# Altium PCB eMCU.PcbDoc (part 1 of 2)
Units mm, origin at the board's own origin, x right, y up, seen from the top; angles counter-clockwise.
Board outline 90 x 58 mm, 2 copper layers (Top Layer, Bottom Layer); 104 components, 112 nets, 449 pads, 70 vias.
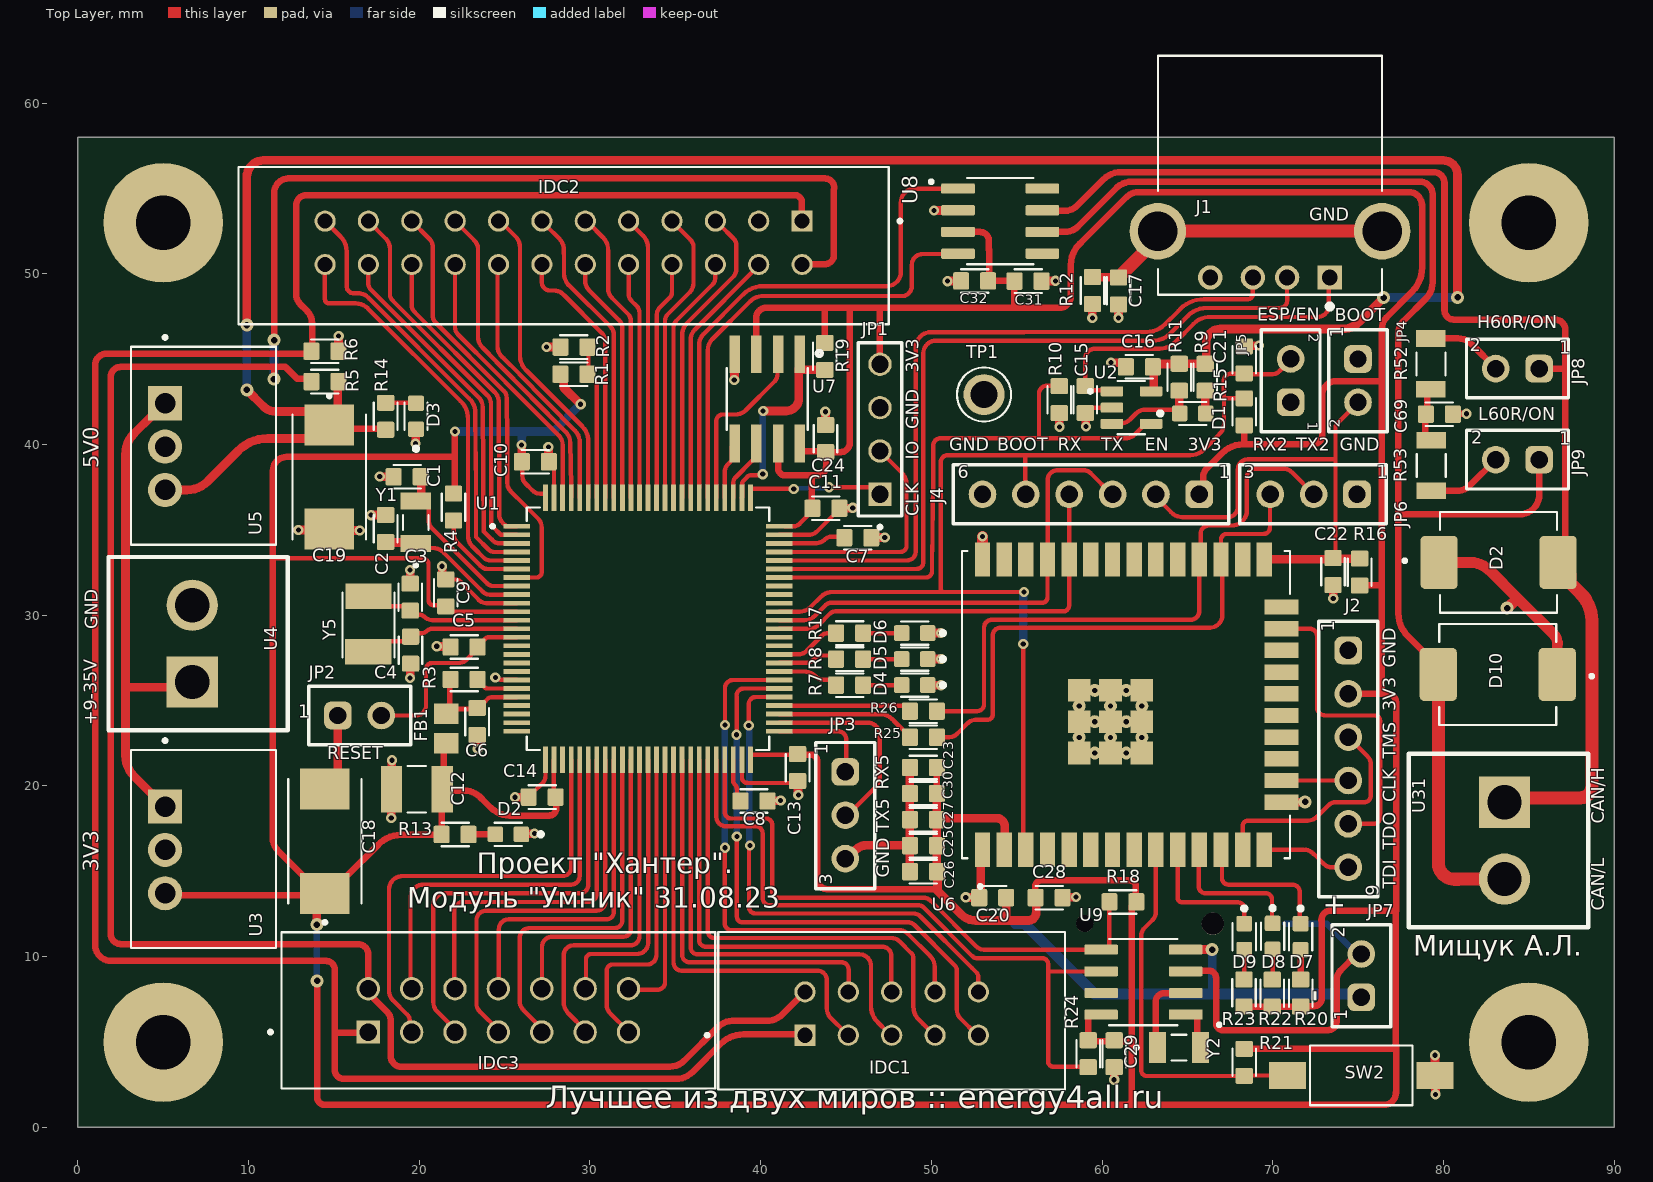
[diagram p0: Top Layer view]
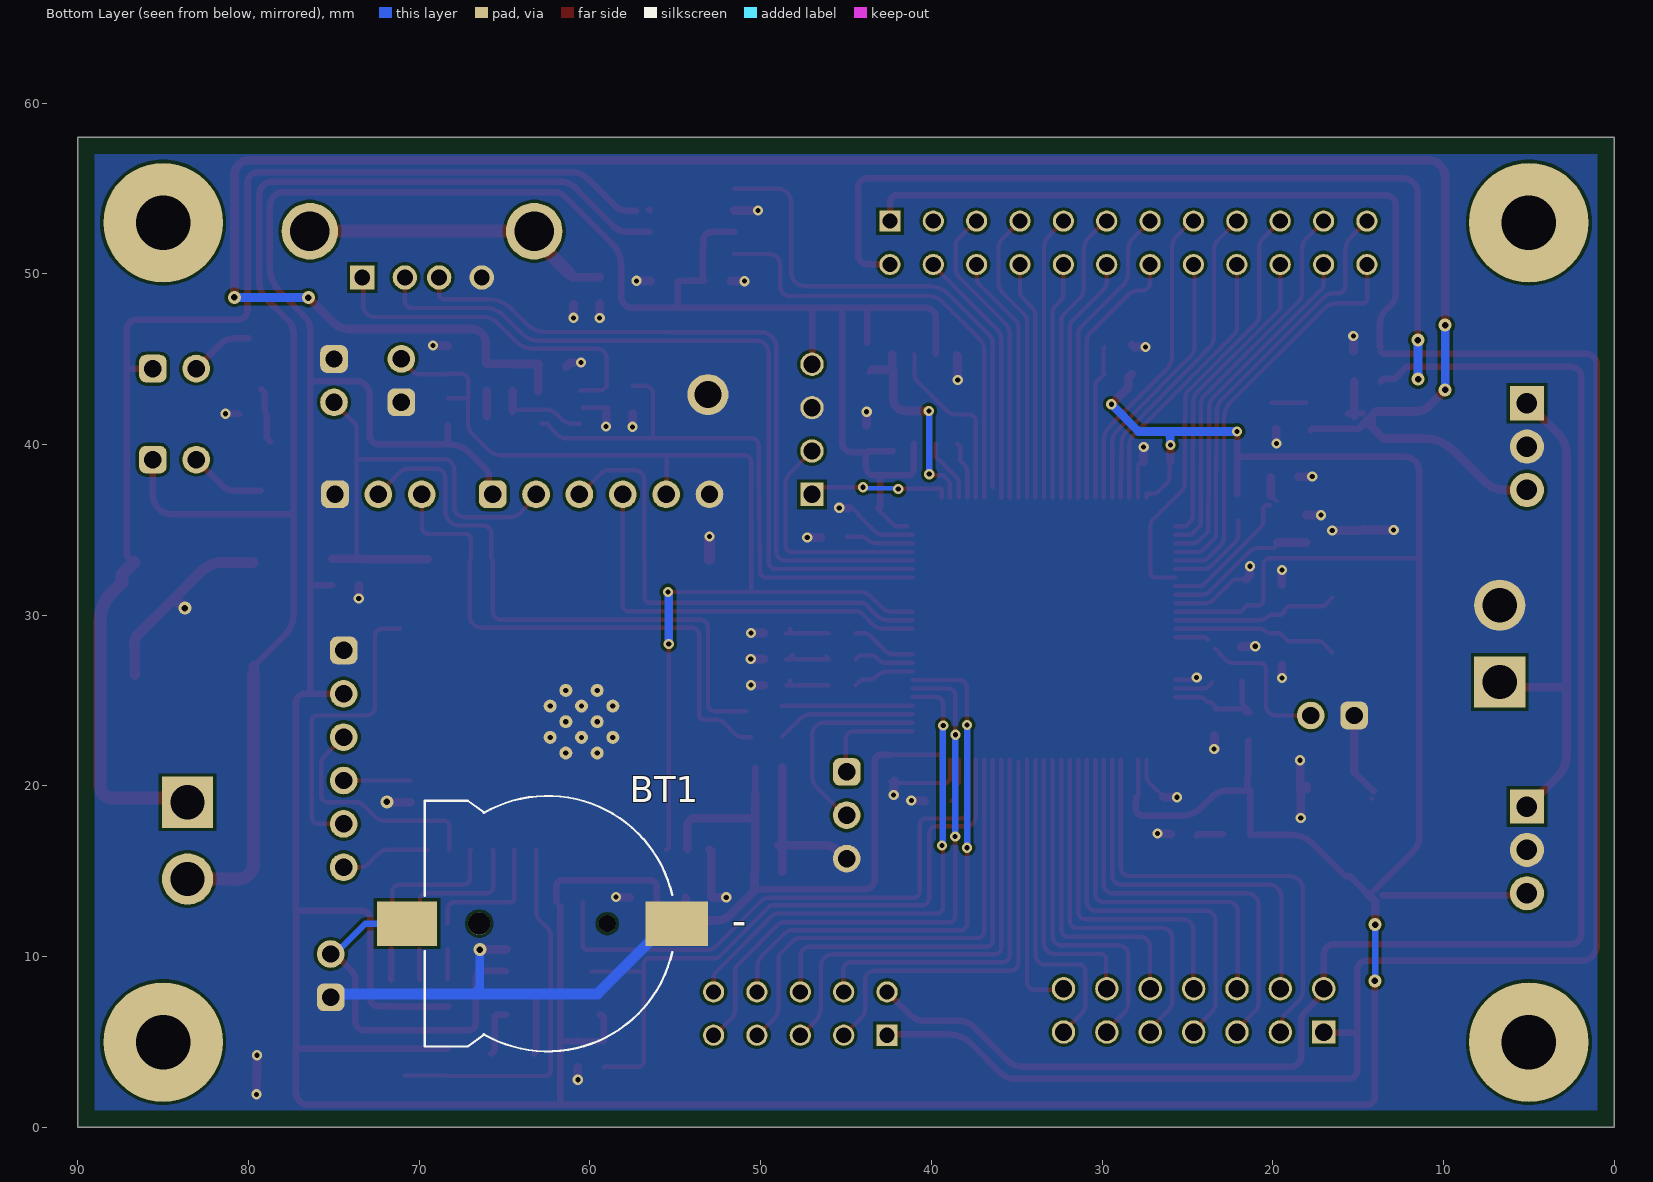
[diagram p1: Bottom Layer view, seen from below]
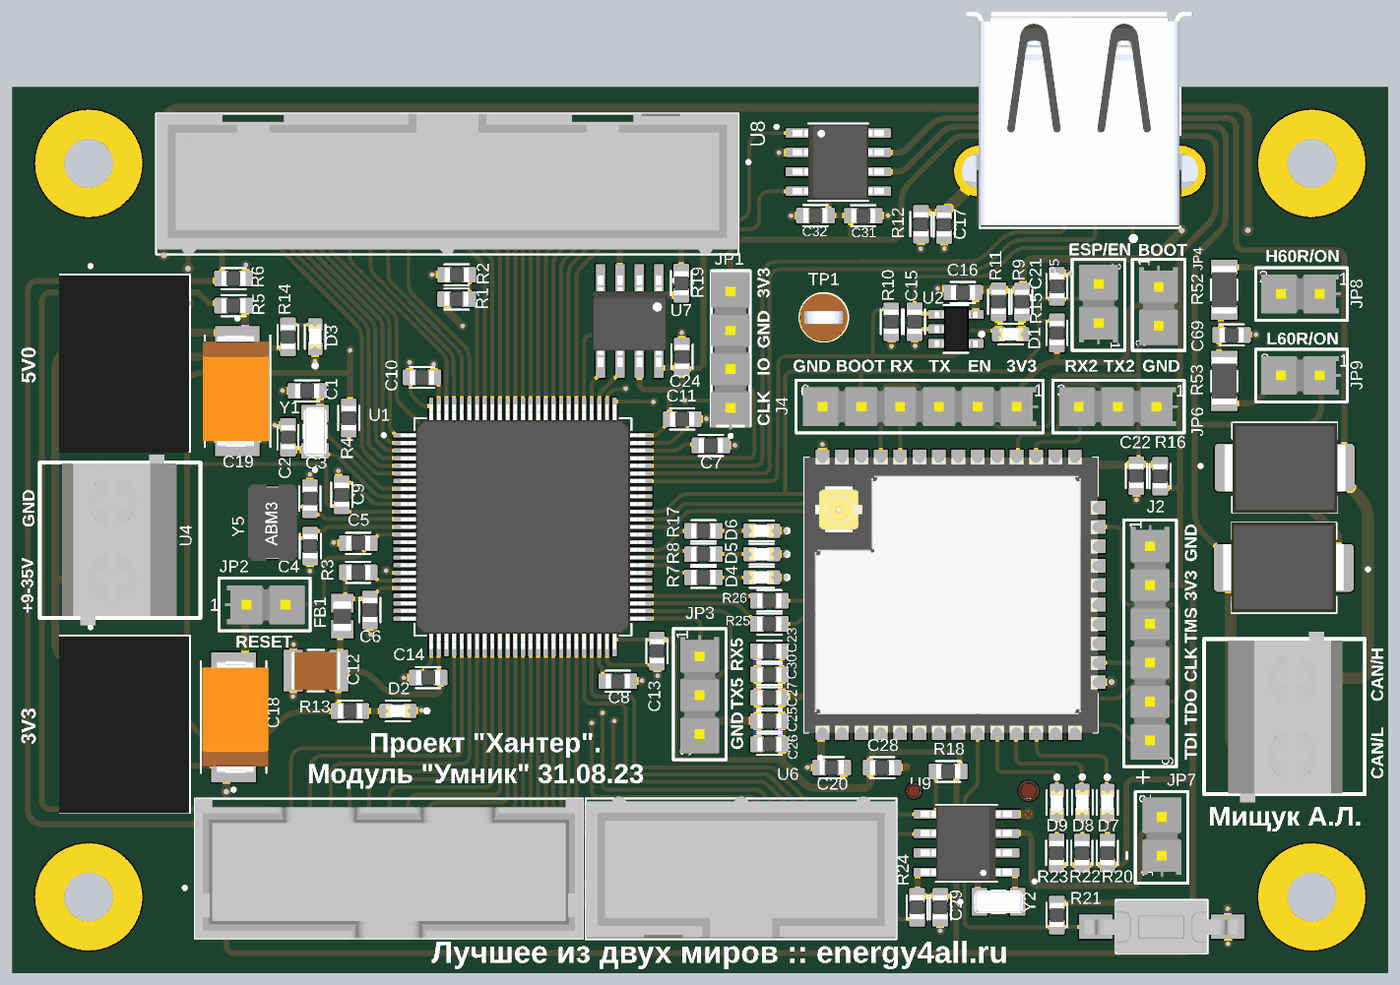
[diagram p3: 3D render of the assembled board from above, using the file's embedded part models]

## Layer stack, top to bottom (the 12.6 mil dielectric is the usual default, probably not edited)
Top Solder: solder mask 0.0102, Solder Resist, Dk 3.5
Top Layer: signal copper 0.0356
Dielectric 1: dielectric 0.32, FR-4, Dk 4.8
Bottom Layer: signal copper 0.0356
Bottom Solder: solder mask 0.0102, Solder Resist, Dk 3.5

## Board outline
0,0 0,58 90,58 90,0

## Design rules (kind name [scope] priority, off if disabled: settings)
Clearance [All] p1: gap=0.178 ignorepadtopadclearanceinfootprint=FALSE except(0: Arc-Hole Track-Hole SMDPad-Hole THPad-Hole Via-Hole Fill-Hole Poly-Hole Region-Hole Text-Hole; 0.152: SMDPad-SMDPad)
HoleSize [All] p1: absolutevalues=TRUE maxlimit=5.08 minlimit=0.025 maxpercent=80.000 minpercent=20.000
MinimumSolderMaskSliver [All] p1 off: minsoldermaskwidth=0.254
PasteMaskExpansion [All] p1 off: expansion=0
PolygonConnect [All] p1: connectstyle=Direct reliefconductorwidth=0.254 reliefentries=4 polygonreliefangle="90 Angle" airgapwidth=0.254
RoomDefinition Can [InComponentClass('Can')] p1: confinementstyle=ConfineOut formatcopy=TRUE lockcomponents=FALSE outline 92.532,16.866 96.52,16.866 96.52,20.066 92.532,20.066
RoomDefinition eMCU [InComponentClass('eMCU')] p2: confinementstyle=ConfineOut formatcopy=TRUE lockcomponents=FALSE outline 92.456,28.626 96.52,28.626 96.52,30.404 92.456,30.404
RoomDefinition eSupply [InComponentClass('eSupply')] p3: confinementstyle=ConfineOut formatcopy=TRUE lockcomponents=FALSE outline 92.507,24.587 96.52,24.587 96.52,26.365 92.507,26.365
RoomDefinition eConnect [InComponentClass('eConnect')] p4: confinementstyle=ConfineOut formatcopy=TRUE lockcomponents=FALSE outline 92.532,26.594 96.52,26.594 96.52,28.372 92.532,28.372
RoomDefinition eUSB [InComponentClass('eUSB')] p5: confinementstyle=ConfineOut formatcopy=TRUE lockcomponents=FALSE outline 92.532,22.733 96.545,22.733 96.545,24.333 92.532,24.333
RoomDefinition eWiFi [InComponentClass('eWiFi')] p6: confinementstyle=ConfineOut formatcopy=TRUE lockcomponents=FALSE outline 92.558,20.828 96.545,20.828 96.545,22.555 92.558,22.555
RoutingVias [All] p1: holewidth=0.711 width=1.27 viastyle="Through Hole" minholewidth=0.711 minwidth=1.27 maxholewidth=0.711 maxwidth=1.27
SilkToSilkClearance [All] p1 off: silktosilkclearance=0.127
SilkToSolderMaskClearance [IsPad] p1 off: minsilkscreentomaskgap=0.254 clearancetoexposedcopper=TRUE
SolderMaskExpansion [All] p1 off: expansion=0.102 istentingtop=FALSE
Width [All] p1: maxlimit=1.27 minlimit=0.254 preferedwidth=0.508
25 further rules are at their usual default settings.

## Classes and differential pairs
component class Can: C31 C32 C69 D2 D10 JP8 JP9 R52 R53 U8 U27 U31
component class eWiFi: C20 C21 C22 C23 C25 C26 C27 C28 C30 D7 D8 D9 J2 J4 JP4 JP5 JP6 R15 R16 R20 R21 R22 R23 SW2 U6
component class eUSB: C15 C16 C17 D1 J1 R9 R10 R11 R12 U2
component class eConnect: IDC1 IDC2 IDC3 R5 R6
component class eSupply: C6 C7 C8 C9 C10 C11 C12 C13 C14 C18 C19 D2 D3 FB1 R3 R4 R13 R14 TP1 U3 U4 U5
component class eMCU: BT1 C1 C2 C3 C4 C5 C24 C29 D4 D5 D6 JP1 JP2 JP3 JP7 R1 R2 R7 R8 R17 R18 R19 R24 R25 R26 U1 U7 U9 Y Y1 Y2 Y5

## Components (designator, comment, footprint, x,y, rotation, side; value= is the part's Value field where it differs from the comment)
BT1 "BC501SM" BAT_BC501SM 62.484,11.938 r0 bottom
C1 "22pF" CAP_0603 19.294,38.113 r0 top
C2 "22pF" CAP_0603 18.033,35.081 r270 top
C3 "22pF" CAP_0603 19.473,31.065 r270 top
C4 "22pF" CAP_0603 19.494,27.953 r90 top
C5 "0.1uF" CAP_0603 22.631,28.143 r0 top
C6 "0.1uF" CAP_0603 23.393,23.774 r90 top
C7 "4.7uF 25V" CAP_0603 45.692,34.544 r180 top
C8 "4.7uF 25V" CAP_0603 39.612,19.119 r180 top
C9 "0.1uF" CAP_0603 21.552,31.312 r270 top
C10 "0.1uF" CAP_0603 26.801,38.996 r180 top
C11 "0.1uF" CAP_0603 43.821,36.267 r180 top
C12 "47uF" CAP_1210 19.863,19.805 r0 top
C13 "0.1uF" CAP_0603 42.164,21.082 r90 top
C14 "0.1uF" CAP_0603 27.203,19.35 r0 top
C15 "0.1uF" CAP_0603 59.015,42.637 r270 top
C16 "0.1uF" CAP_0603 62.182,44.55 r180 top
C17 "0.01uF" CAP_0603 60.96,48.994 r90 top
C18 "100uF" CAP_TYPE_D 14.478,16.764 r90 top
C19 "100uF" CAP_TYPE_D 14.732,38.1 r270 top
C20 "0.1uF" CAP_0603 53.594,13.462 r0 top
C21 "0.1uF" CAP_0603 68.326,44.958 r270 top
C22 "0.1uF" CAP_0603 73.525,32.555 r90 top
C23 "4.7uF" CAP_0603 49.53,21.082 r0 top
C24 "0.1uF" CAP_0603 43.802,40.346 r270 top
C25 "4.7uF" CAP_0603 49.53,16.51 r0 top
C26 "4.7uF" CAP_0603 49.53,14.986 r0 top
C27 "4.7uF" CAP_0603 49.53,18.034 r0 top
C28 "0.1uF" CAP_0603 56.896,13.462 r180 top
C29 "0.1uF" CAP_0603 60.706,4.318 r90 top
C30 "4.7uF" CAP_0603 49.53,19.558 r180 top
C31 "2.2uF" CAP_0603 55.662,49.572 r180 top
C32 "0.1uF" CAP_0603 52.535,49.582 r0 top
C69 "0.047uF" CAP_0603 79.753,41.774 r180 top
D1 "led_0603" led_0603 65.307,41.821 r0 top
D2 "SM15T30CA" SM15T30CA 83.225,33.095 r0 top
D2 "led_0603" led_0603 25.221,17.17 r180 top
D3 "led_0603" led_0603 19.812,41.656 r90 top
D4 "led_0603" led_0603 49.022,25.908 r180 top
D5 "led_0603" led_0603 49.022,27.432 r180 top
D6 "led_0603" led_0603 49.022,28.956 r180 top
D7 "led_0603" led_0603 71.628,11.174 r270 top
D8 "led_0603" led_0603 69.989,11.193 r270 top
D9 "led_0603" led_0603 68.326,11.176 r270 top
D10 "SM15T30CA" SM15T30CA 83.177,26.533 r180 top
FB1 "LI0805H151R-10" LI0805H151R-10 21.59,23.368 r90 top
IDC1 "IDC-10" IDC-10 42.596,5.403 r0 top
IDC2 "IDC-24" IDC-24 42.428,53.086 r180 top
IDC3 "IDC-14" IDC-14 17.018,5.588 r180 top
J1 "292303-1" TE_292303-1 73.334,49.784 r180 top
J2 "UART" TSW-106-07-F-S 74.422,21.59 r270 top
J4 "TSW-106-07-F-S" TSW-106-07-F-S 59.344,37.084 r180 top
JP1 "ST-LINK" TSW-104-07-F-S 46.99,37.084 r90 top
JP2 "RESET" TSW-102-07-F-S 16.51,24.13 r0 top
JP3 "TSW-103-07-F-S" TSW-103-07-F-S 44.958,18.288 r270 top
JP4 "RESET" TSW-102-07-F-S 74.987,43.739 r270 top
JP5 "RESET" TSW-102-07-F-S 71.044,43.745 r90 top
JP6 "TSW-103-07-F-S" TSW-103-07-F-S 72.39,37.084 r180 top
JP7 "TSW-102-07-F-S" TSW-102-07-F-S 75.184,8.89 r90 top
JP8 "TSW-102-07-F-S" TSW-102-07-F-S 84.328,44.45 r180 top
JP9 "TSW-102-07-F-S" TSW-102-07-F-S 84.328,39.116 r180 top
R1 "DNP" RESC1608X50N 29.064,44.12 r180 top
R2 "10k" RESC1608X50N 29.068,45.708 r0 top
R3 "1k" RESC1608X50N 22.629,26.238 r0 top
R4 "1k" RESC1608X50N 22.009,36.338 r270 top
R5 "0R" RESC1608X50N 14.478,43.688 r180 top
R6 "0R" RESC1608X50N 14.478,45.466 r180 top
R7 "10K" RESC1608X50N 45.212,25.908 r180 top
R8 "10K" RESC1608X50N 45.212,27.432 r180 top
R9 "10k" RESC1608X50N 66.04,43.942 r90 top
R10 "10k" RESC1608X50N 57.493,42.631 r90 top
R11 "100k" RESC1608X50N 64.516,43.942 r90 top
R12 "1MOM" RESC1608X50N 59.436,49.022 r270 top
R13 "10K" RESC1608X50N 22.102,17.162 r180 top
R14 "10K" RESC1608X50N 18.034,41.656 r270 top
R15 "10K" RESC1608X50N 68.326,41.91 r270 top
R16 "10K" RESC1608X50N 75.083,32.531 r270 top
R17 "10K" RESC1608X50N 45.212,28.956 r180 top
R18 "10K" RESC1608X50N 61.214,13.208 r0 top
R19 "4.7K" RESC1608X50N 43.759,45.164 r270 top
R20 "10K" RESC1608X50N 71.628,7.874 r270 top
R21 "10K" RESC1608X50N 68.326,3.81 r90 top
R22 "10K" RESC1608X50N 69.967,7.87 r270 top
R23 "10K" RESC1608X50N 68.312,7.877 r270 top
R24 "10K" RESC1608X50N 59.182,4.318 r90 top
R25 "0R" RESC1608X50N 49.53,22.86 r180 top
R26 "0R" RESC1608X50N 49.53,24.384 r180 top
R52 "60R" RES_1206 79.262,44.73 r90 top
R53 "60R" RES_1206 79.275,38.761 r90 top
SW2 "SW_6.0x3.7" SW_6.0x3.7 75.184,3.048 r0 top
TP1 "TP_RED" TP_RED 53.086,42.926 r0 top
U1 "STM32H750VBT6" STM32H750VBT6 33.401,29.21 r0 top
U2 "STMPS2151STR" STMPS2151STR 61.722,42.164 r0 top
U3 "R-78E5.0-1.0" R-78E5.0-1.0 7.366,16.256 r270 top
U4 "DG129-5.0-02P" DG129-5.0-02P 6.706,28.336 r90 top
U5 "R-78E5.0-1.0" R-78E5.0-1.0 7.366,39.878 r270 top
U6 "ESP32-WROOM-32U" ESP32-WROOM-32U 61.402,24.766 r90 top
U7 "FM25Q16" FM25Q16 40.386,42.672 r180 top
U8 "SN65HVD232D" SN65HVD232D 54.03,53.086 r0 top
U9 "DS1338Z-33" DS1338Z-33 62.419,8.509 r180 top
U31 "DG129-5.0-02P" DG129-5.0-02P 83.566,16.8 r270 top
Y1 "32kHz" NX3215SA 19.801,35.441 r90 top
Y2 "32kHz" NX3215SA 64.506,4.677 r0 top
Y5 "8MHz" NX3225GD 17.026,29.422 r90 top

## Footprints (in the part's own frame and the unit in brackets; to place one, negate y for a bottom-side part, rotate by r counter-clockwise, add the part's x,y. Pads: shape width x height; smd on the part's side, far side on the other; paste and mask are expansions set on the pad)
BAT_BC501SM [mm]
  rect 3.66x2.6 smd: N(-7.57,0)
  rect 3.54x2.6 smd: P(8.23,0)
  round 1 hole 1 unplated: ""(-3.5,0)
  round 1.3 hole 1.3 unplated: ""(4,0)
  silkscreen extent -7.31,-7.48 7.18,7.48, body extent -8.5,-7.49 9.5,7.49, height 4
CAP_0603 [mm]
  rrect20% 0.94x1.02 smd: 1(-0.79,0) 2(0.79,0)
  silkscreen extent -0.8,-0.69 0.8,0.69, body extent -0.8,-0.47 0.8,0.48, height 0.78
CAP_1210 [mm]
  rect 1.24x2.73 smd: 1(-1.485,0) 2(1.485,0)
  silkscreen extent -0.54,-1.36 0.54,1.36, body extent -1.6,-1.25 1.6,1.25, height 1.97
CAP_TYPE_D [mm]
  rect 2.4x2.9 smd: 1(-3.05,0) 2(3.05,0)
  silkscreen extent -4.85,-2.15 3.65,2.15, body extent -3.65,-2.27 3.65,2.03, height 3.1
DG129-5.0-02P [mm]
  rect 3x3 hole 2: 1(-2.25,0)
  round 3 hole 2: 2(2.25,0)
  silkscreen extent -5.08,-5.6 5.08,4.9, body extent -5.55,-4.05 5.61,3.45, height 10.08
DS1338Z-33 [mm]
  rect 1.97x0.59 smd: 1(-2.475,1.905)
  rrect25% 1.97x0.59 smd: 2(-2.475,0.635) 3(-2.475,-0.635) 4(-2.475,-1.905) 5(2.475,-1.905) 6(2.475,-0.635) 7(2.475,0.635) 8(2.475,1.905)
  silkscreen extent -4.54,-2.52 2,2.59, body extent -2.98,-2.46 3.02,2.44, height 1.75
ESP32-WROOM-32U [mm]
  rect 2x0.9 smd: 1(-8.5,8.41) 2(-8.5,7.14) 3(-8.5,5.87) 4(-8.5,4.6) 5(-8.5,3.33) 6(-8.5,2.06) 7(-8.5,0.79) 8(-8.5,-0.48) 9(-8.5,-1.75) 10(-8.5,-3.02) 11(-8.5,-4.29) 12(-8.5,-5.56) 13(-8.5,-6.83) 14(-8.5,-8.1) 25(8.5,-8.1) 26(8.5,-6.83) 27(8.5,-5.56) 28(8.5,-4.29) 29(8.5,-3.02) 30(8.5,-1.75) 31(8.5,-0.48) 32(8.5,0.79) 33(8.5,2.06) 34(8.5,3.33) 35(8.5,4.6) 36(8.5,5.87) 37(8.5,7.14) 38(8.5,8.41)
  rect 0.9x2 smd: 15(-5.715,-9.1) 16(-4.445,-9.1) 17(-3.175,-9.1) 18(-1.905,-9.1) 19(-0.635,-9.1) 20(0.635,-9.1) 21(1.905,-9.1) 22(3.175,-9.1) 23(4.445,-9.1) 24(5.715,-9.1)
  rect 1.33x1.33 smd: G.1(0.835,2.745) G.2(-1,2.745) G.4(-2.835,2.745) G.5(0.835,0.91) G.6(-1,0.91) G.7(-2.835,0.91) G.8(0.835,-0.925) G.9(-1,-0.925) G.10(-2.835,-0.925)
  round 0.762 hole 0.305: G.11(-0.082,2.745) G.12(-1.917,2.745) G.13(0.835,1.827) G.14(-1,1.827) G.15(-2.835,1.827) G.16(-0.082,0.91) G.17(-1.917,0.91) G.18(0.835,-0.008) G.19(-1,-0.008) G.20(-2.835,-0.008) G.21(-0.082,-0.925) G.22(-1.917,-0.925)
  silkscreen extent -10.75,-9.6 9,9.6, body extent -9.02,-9.6 8.98,9.6, height 3.3
FM25Q16 [mil]
  rect 24x87 smd: 1(-75,-103) 2(-25,-103) 3(25,-103) 4(75,-103) 5(75,103) 6(25,103) 7(-25,103) 8(-75,103)
  silkscreen extent -126,-111 93,71, body extent -96,-118 96,118, height 69
IDC-10 [mm]
  rect 1.24x1.24 hole 0.89: 1(0,0)
  round 1.24 hole 0.89: 2(0,2.54) 3(2.54,0) 4(2.54,2.54) 5(5.08,0) 6(5.08,2.54) 7(7.62,0) 8(7.62,2.54) 9(10.16,0) 10(10.16,2.54)
  silkscreen extent -5.83,-3.17 15.24,6.04, body extent -5.08,-3.05 15.24,6.17, height 8.89
IDC-14 [mm]
  rect 1.37x1.37 hole 1.02: 1(0,0)
  round 1.37 hole 1.02: 2(0,-2.54) 3(-2.54,0) 4(-2.54,-2.54) 5(-5.08,0) 6(-5.08,-2.54) 7(-7.62,0) 8(-7.62,-2.54) 9(-10.16,0) 10(-10.16,-2.54) 11(-12.7,0) 12(-12.7,-2.54) 13(-15.24,0) 14(-15.24,-2.54)
  silkscreen extent -20.32,-5.84 5.83,3.3, body extent -20.32,-5.84 5.08,3.3, height 9.25
IDC-24 [mm]
  rect 1.24x1.24 hole 0.89: 1(0,0)
  round 1.24 hole 0.89: 2(0,2.54) 3(2.54,0) 4(2.54,2.54) 5(5.08,0) 6(5.08,2.54) 7(7.62,0) 8(7.62,2.54) 9(10.16,0) 10(10.16,2.54) 11(12.7,0) 12(12.7,2.54) 13(15.24,0) 14(15.24,2.54) 15(17.78,0) 16(17.78,2.54) 17(20.32,0) 18(20.32,2.54) 19(22.86,0) 20(22.86,2.54) 21(25.4,0) 22(25.4,2.54) 23(27.94,0) 24(27.94,2.54)
  silkscreen extent -5.83,-3.18 33.02,6.04, body extent -5.08,-3.17 33.02,6.05, height 8.99
led_0603 [mm]
  rrect25% 0.91x0.93 smd: A(0.76,0) C(-0.76,0)
  silkscreen extent -2.02,-0.68 0.8,0.68, body extent -0.78,-0.4 0.82,0.4, height 0.65
LI0805H151R-10 [mm]
  rect 1.2x1.45 smd: 1(-0.85,0) 2(0.85,0)
  body extent -1,-0.62 1,0.63, height 1.15
NX3215SA [mm]
  rect 1x1.8 smd: 1(-1.25,0) 2(1.25,0)
  silkscreen extent -2.6,-0.75 0.43,0.75, body extent -1.6,-0.75 1.6,0.75, height 0.9
NX3225GD [mm]
  rect 1.5x2.7 smd: 1(-1.552,0.007) 2(1.686,0.002)
  silkscreen extent -1.91,-1.52 1.91,1.52, body extent -2.43,-1.59 2.57,1.61, height 1.3
R-78E5.0-1.0 [mm]
  rect 2x2 hole 1.2: 1(-2.54,-2.25)
  round 2 hole 1.2: 2(0,-2.25) 3(2.54,-2.25)
  silkscreen extent -6.5,-4.25 5.75,4.25, body extent -5.8,-4.31 5.8,4.19, height 10.41
RES_1206 [mm]
  rect 0.97x1.73 smd: 1(-1.48,0) 2(1.48,0)
  silkscreen extent -0.67,-0.85 0.67,0.85, body extent -1.55,-0.8 1.55,0.8, height 0.65
RESC1608X50N [mm]
  rrect20% 0.94x1.02 smd: 1(-0.79,0) 2(0.79,0)
  silkscreen extent -0.8,-0.69 0.8,0.69, body extent -0.79,-0.48 0.81,0.47, height 0.78
SM15T30CA [mm]
  rrect25% 2.18x3.12 smd: 1(-3.485,0) 2(3.485,0)
  silkscreen extent -5.6,-2.95 3.43,2.95, body extent -3.94,-2.98 4,2.92, height 2.6
SN65HVD232D [mm]
  rrect25% 1.97x0.6 smd: 1(-2.47,1.905) 2(-2.47,0.635) 3(-2.47,-0.635) 4(-2.47,-1.905) 5(2.47,-1.905) 6(2.47,-0.635) 7(2.47,0.635) 8(2.47,1.905)
  silkscreen extent -4.14,-2.52 1.95,2.52, body extent -3,-2.45 3,2.45, height 1.75
STM32H750VBT6 [mm]
  rrect7% 1.56x0.28 smd: 1(-7.68,6) 2(-7.68,5.5) 3(-7.68,5) 4(-7.68,4.5) 5(-7.68,4) 6(-7.68,3.5) 7(-7.68,3) 8(-7.68,2.5) 9(-7.68,2) 10(-7.68,1.5) 11(-7.68,1) 12(-7.68,0.5) 13(-7.68,0) 14(-7.68,-0.5) 15(-7.68,-1) 16(-7.68,-1.5) 17(-7.68,-2) 18(-7.68,-2.5) 19(-7.68,-3) 20(-7.68,-3.5) 21(-7.68,-4) 22(-7.68,-4.5) 23(-7.68,-5) 24(-7.68,-5.5) 25(-7.68,-6) 51(7.68,-6) 52(7.68,-5.5) 53(7.68,-5) 54(7.68,-4.5) 55(7.68,-4) 56(7.68,-3.5) 57(7.68,-3) 58(7.68,-2.5) 59(7.68,-2) 60(7.68,-1.5) 61(7.68,-1) 62(7.68,-0.5) 63(7.68,0) 64(7.68,0.5) 65(7.68,1) 66(7.68,1.5) 67(7.68,2) 68(7.68,2.5) 69(7.68,3) 70(7.68,3.5) 71(7.68,4) 72(7.68,4.5) 73(7.68,5) 74(7.68,5.5) 75(7.68,6)
  rrect7% 0.28x1.56 smd: 26(-6,-7.68) 27(-5.5,-7.68) 28(-5,-7.68) 29(-4.5,-7.68) 30(-4,-7.68) 31(-3.5,-7.68) 32(-3,-7.68) 33(-2.5,-7.68) 34(-2,-7.68) 35(-1.5,-7.68) 36(-1,-7.68) 37(-0.5,-7.68) 38(0,-7.68) 39(0.5,-7.68) 40(1,-7.68) 41(1.5,-7.68) 42(2,-7.68) 43(2.5,-7.68) 44(3,-7.68) 45(3.5,-7.68) 46(4,-7.68) 47(4.5,-7.68) 48(5,-7.68) 49(5.5,-7.68) 50(6,-7.68) 76(6,7.68) 77(5.5,7.68) 78(5,7.68) 79(4.5,7.68) 80(4,7.68) 81(3.5,7.68) 82(3,7.68) 83(2.5,7.68) 84(2,7.68) 85(1.5,7.68) 86(1,7.68) 87(0.5,7.68) 88(0,7.68) 89(-0.5,7.68) 90(-1,7.68) 91(-1.5,7.68) 92(-2,7.68) 93(-2.5,7.68) 94(-3,7.68) 95(-3.5,7.68) 96(-4,7.68) 97(-4.5,7.68) 98(-5,7.68) 99(-5.5,7.68) 100(-6,7.68)
  silkscreen extent -9.2,-7.1 7.1,7.1, body extent -8,-8 8,8, height 1.49
STMPS2151STR [mm]
  rrect25% 1.32x0.59 smd: 1(-1.145,0.95) 2(-1.145,0) 3(-1.145,-0.95) 4(1.145,-0.95) 5(1.145,0.95)
  silkscreen extent -2.51,-1.57 0.8,1.57, body extent -1.38,-1.46 1.42,1.44, height 1.15
SW_6.0x3.7 [mm]
  rect 2.18x1.6 smd: 1(-4.318,0) 2(4.318,0)
  silkscreen extent -3,-1.75 3,1.75, body extent -5.02,-1.77 4.95,1.73, height 4.37
TE_292303-1 [mm]
  rect 1.428x1.428 hole 0.92: 1(0,0)
  round 1.428 hole 0.92: 2(2.5,0) 3(4.5,0) 4(7,0)
  round 3.316 hole 2.3: SH1(-3.07,-2.71) SH2(10.07,-2.71)
  silkscreen extent -3.07,-12.99 10.06,1.85, body extent -4.44,-13.15 11.56,0.85, height 7.78
TP_RED [mm]
  round 2.4 hole 1.6: 1(0,0)
  silkscreen extent -1.59,-1.58 1.59,1.58, body extent -1.6,-1.61 1.57,1.57, height 8.13
TSW-102-07-F-S [mm]
  rrect50% 1.62x1.62 hole 1.02: 1(-1.27,0)
  round 1.62 hole 1.02: 2(1.27,0)
  silkscreen extent -2.99,-1.72 2.98,1.72, body extent -2.58,-1.28 2.62,1.26, height 8.38
TSW-103-07-F-S [mm]
  rrect50% 1.62x1.62 hole 1.02: 1(-2.54,0)
  round 1.62 hole 1.02: 2(0,0) 3(2.54,0)
  silkscreen extent -4.26,-1.72 4.32,1.72, body extent -3.85,-1.27 3.9,1.27, height 8.38
TSW-104-07-F-S [mm]
  rect 1.37x1.37 hole 1.02: 1(0,0)
  round 1.37 hole 1.02: 2(2.54,0) 3(5.08,0) 4(7.62,0)
  silkscreen extent -2.02,-1.27 8.89,1.27, body extent -1.49,-1.25 8.8,1.29, height 9.27
TSW-106-07-F-S [mm]
  rrect50% 1.62x1.62 hole 1.02: 1(-6.35,0)
  round 1.62 hole 1.02: 2(-3.81,0) 3(-1.27,0) 4(1.27,0) 5(3.81,0) 6(6.35,0)
  silkscreen extent -8.07,-1.72 8.07,1.72, body extent -7.75,-1.27 7.62,1.27, height 8.38

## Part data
BT1: library part BAT_BC501SM, "BATTERY HOLDER COIN 12MM SMD", Package=None
C1 C2 C3 C4 C5 C6 C7 C8 C9 C10 C11 C13 C14 C15 C16 C17 C20 C21 C22 C23 C24 C25 C26 C27 C28 C29 C30 C31 C32 C69: library part CAP_0603
C12: library part CAP_1210
C18 C19: library part CAP_TYPE_D, Package=None
D1 D2 D3 D4 D5 D6 D7 D8 D9: "LED Indication - Discrete 3.1V 0603 _1608 Metric_", Package="0603 Lite-On"
D2 D10: "1500 W, 25.6 V TVS", Package="DO-214AB-214 ON Semiconductor"
FB1: "150 Ohms @ 100MHz 1 Power, Signal Line Ferrite Bead 0805 (2012 Metric) 800mA 150mOhm", Package="0805 Laird"
IDC1: "Header, Pin, Idc, Amp-Latch, 10 Pos, Low Profile, Pcb, Vertical, Blue", Package=None
IDC2: "IDC LOW PRO HDR 24P VERT BLUE", Package=None
IDC3: "HEADER, PIN, AMP-LATCH, 14 POS, 2.54 X 2.54, VERTICAL, LOW PROFILE, PCB", Package=None
J1: "Conn; Data; USB; Recept; 2.0; 4 Pos; 1 Port; Rt Angle; A Ser; Tin over Copper", Package=None
J2: library part TSW-106-07-F-S
JP1: library part TSW-104-07-F-S, "Connector Header Through Hole 4 position 0.100 (2.54mm)", Package=None
JP2 JP4 JP5: library part TSW-102-07-F-S
R1 R2 R3 R4 R5 R6 R7 R8 R9 R10 R11 R12 R13 R14 R15 R16 R17 R18 R19 R20 R21 R22 R23 R24 R25 R26: library part RES_0603, "1% 0.1W", Package=None
R52 R53: library part RES_1206, "1% 1/4W", Package=None
SW2: "Switch Tactile OFF (ON) SPST Rectangular Button Gull Wing 0.05A 12VDC SMD Loose Piece", Package=None
TP1: "RF EMI Absorbing Sheet - Polyurethane Foam 24.000 (609.60mm) X 24.000 (609.60mm) X 0.252 (6.40mm)", Package="TO-66 Aeroflex"
U1: "ARM Cortex-M7 STM32H7 Microcontroller IC 32-Bit 480MHz 128KB _128K x 8_ FLASH 100-LQFP _14x14_", Package="LQFP-100 STMicroelectronics"
U2: library part STMPS2141STR, "Power Switch/Driver 1:1 N-Channel 500mA SOT-23-5", Package="SOT-23 STMicroelectronics"
U3 U5: "1A DC/DC-Converter SIP3", Package="SIP-3 Recom Power"
U4 U31: "DG129-5.0-02P-14-00A(H)"
U6: "Bluetooth, WiFi 802.11b/g/n, Bluetooth v4.2 +EDR, Class 1, 2 and 3 Transceiver Module 2.4GHz ~ 2.5GHz Antenna Not Included, U.FL Surface Mount", Package="Module Espressif Systems"
U7: "Serial Flash Memory with 4KB Sectors SPI SOIC-8", Package="SOIC-8 Ramtron"
U8: "3.3 V CAN Transceiver", Package="SOIC-8 Texas Instruments"
U9: "Real Time Clock (RTC) IC Clock/Calendar 56B IÂ²C, 2-Wire Serial 8-SOIC (0.154, 3.90mm Width)", Package="SOIC-8 Maxim"
Y1 Y2: library part NX3215SA-32.768K-STD-MUA-8, "32.768 kHz Â±20ppm Crystal 12.5pF 70 kOhms 2-SMD, No Lead", Package="SMD-2 NDK"
Y5: library part NX3225GD, "8MHz Â±20ppm Crystal 18pF 140 Ohms 2-SMD, No Lead", Package="SMD-2 Abracon"

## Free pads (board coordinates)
  round 7 hole 3.2: 1(5,5) 2(5,53) 3(85,53) 4(85,5)

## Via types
v1: diameter 0.6, hole 0.3, Top Layer to Bottom Layer, tented both sides, 59 vias
v2: diameter 0.762, hole 0.381, Top Layer to Bottom Layer, tented both sides, 11 vias

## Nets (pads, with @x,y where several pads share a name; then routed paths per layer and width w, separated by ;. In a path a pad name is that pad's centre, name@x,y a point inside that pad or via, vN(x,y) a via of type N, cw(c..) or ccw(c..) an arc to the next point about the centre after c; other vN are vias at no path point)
3V3: C9.2 C10.2 C11.2 C12.2 C13.2 C14.2 C18.1 C20.2 C23.2 C24.2 C25.2 C26.2 C27.2 C28.2 C29.2 C30.1 C31.2 C32.2 FB1.1 J2.2 J4.1 JP1.4 R1.2 R4.1 R13.2 R15.2 R16.2 R18.2 R19.1 R20.2 R21.2 R22.2 R23.2 R24.2 U1.11 U1.27 U1.50 U1.75 U1.100 U3.3 U6.2 U7.3 U7.7 U7.8 U8.3 U9.8 | length 420.9
  Top Layer w0.254: 11.43,33.343 20.178,33.343 cw(c20.178,32.974) 20.548,32.974 20.548,30.88 ccw(c20.845,30.88) 20.845,30.582 21.491,30.582 C9.2@21.552,30.522 21.876,30.198 U1.11@25.709,30.198 ; C10.2@26.011,38.996 26.042,38.965 26.042,38.252 26.04,38.25 26.04,38.189 ccw(c26.733,38.189) 26.214,37.73 ccw(c26.733,38.189) 26.243,37.699 ; 26.244,37.7 26.614,37.33 26.617,37.327 ccw(c27.094,37.776) 27.094,37.12 ; 27.095,37.12 27.388,37.12 27.401,37.107 U1.100@27.401,36.89 ; U1.27@27.901,21.53 27.889,21.518 27.889,19.454 C14.2@27.993,19.35 ; U1.50@39.401,21.53 39.401,21.811 39.414,21.824 C13.2@42.4,21.824 ; U1.75@41.424,35.208 41.941,35.208 ccw(c41.941,35.652) 42.255,35.338 ; 42.29,35.369 C11.2@43.183,36.262
  Top Layer w0.381: U3.3@4.354,13.513 4.43,13.589 C18.1@13.591,13.589 ; v2(14.021,8.585) 14.021,1.796 ccw(c14.496,1.796) 14.496,1.321 61.549,1.321 ; C18.1@14.046,13.892 14.046,13.896 13.219,14.724 13.214,14.724 11.747,16.191 cw(c12.533,16.98) 11.427,17.116 ccw(c11.049,17.161) 11.43,17.161 11.43,33.343 11.43,38.47 cw(c12.234,38.47) 12.234,39.274 22.098,39.274 ; C18.1@14.478,13.714 15.488,14.724 15.764,14.724 17.554,16.513 cw(c18.942,15.267) 18.942,17.133 21.284,17.133 R13.2@21.312,17.162 ; R13.2@21.329,17.178 21.329,19.786 C12.2@21.348,19.805 21.425,19.728 22.661,19.728 cw(c22.661,18.452) 23.564,19.354 ; FB1.1@21.412,22.67 21.438,22.645 C12.2@21.438,20.62 ; C12.2@21.5,19.939 C12.2@21.5,20.472 ; R4.1@22.098,37.084 22.098,39.274 ; v1(22.098,40.767) 22.098,39.274 ; 23.568,19.358 23.876,19.05 24.194,18.732 ccw(c25.316,19.854) 25.316,18.267 27.621,18.267 ccw(c27.621,18.673) 28.027,18.673 28.027,19.031 C14.2@27.993,19.35 ; U7.3@39.736,45.303 39.736,47.417 cw(c40.325,47.417) 40.325,48.006 43.768,48.006 ; U7.7@41.021,40.056 41.021,39.141 41.021,38.613 ccw(c41.44,38.613) 41.44,38.194 42.999,38.194 ; U7.8@42.274,39.596 C24.2@43.717,39.596 ; C13.2@42.418,21.844 42.926,21.844 cw(c42.926,21.452) 43.318,21.452 43.318,14.532 ccw(c43.884,14.532) 43.884,13.966 50.351,13.966 ; C11.2@43.031,36.267 42.999,36.299 42.999,38.194 ; C24.2@43.664,39.56 44.697,39.56 ccw(c44.697,40.075) 45.212,40.075 45.212,48.006 ; R19.1@43.759,45.954 R19.1@43.787,45.981 ; R19.1@43.768,45.97 43.768,48.006 ; C24.2@43.802,39.556 43.835,39.523 43.835,38.694 ; 43.83,38.694 cw(c43.33,38.694) 43.818,38.584 cw(c43.33,38.694) 43.44,38.206 cw(c43.33,38.694) 43.33,38.194 42.999,38.194 ; JP1.4@46.99,44.704 46.99,48.006 ; C30.1@50.32,19.558 C23.2@50.32,21.082 ; U8.3@51.56,52.451 52.837,52.451 52.838,52.451 cw(c52.838,51.914) 53.375,51.914 53.375,51.416 ; C32.2@53.27,49.595 C31.2@54.61,49.595 ; C32.2@53.325,49.582 53.381,49.638 53.381,51.416 ; C31.2@54.85,49.55 54.85,48.006 ; 56.09,14.121 cw(c56.447,14.121) 56.096,14.185 cw(c56.447,14.121) 56.447,14.478 61.595,14.478 cw(c61.595,14.097) 61.976,14.097 R18.2@61.976,13.208 ; C28.2@56.096,13.214 56.096,14.121 ; 58.787,51.853 61.416,54.483 ; 58.788,51.852 58.679,51.743 ccw(c59.916,50.505) 58.166,50.505 58.166,48.673 cw(c57.499,48.673) 57.499,48.006 54.85,48.006 ; R24.2@59.182,5.051 60.649,5.051 C29.2@60.706,5.108 60.766,5.048 61.742,5.048 ; R24.2@59.182,5.108 59.203,5.129 59.203,6.499 59.307,6.604 U9.8@59.436,6.604 ; 61.459,54.526 cw(c62.149,53.751) 62.149,54.788 77.972,54.788 cw(c77.972,54.034) 78.726,54.034 ; 61.742,5.108 61.742,5.048 ; 61.75,5.108 R18.2@61.75,12.954 ; J4.1@65.694,37.084 65.928,37.318 65.928,38.11 cw(c66.617,38.11) 66.128,38.595 ; 66.205,38.672 67.044,39.511 ; 67.048,39.507 cw(c68.25,38.305) 68.25,40.005 ; R23.2@68.312,7.087 68.315,7.083 69.964,7.083 R22.2@69.967,7.08 R20.2@71.374,7.08 ; R21.2@68.326,4.6 76.993,4.6 77.212,4.819 ; 68.326,40.005 72.339,40.005 ccw(c72.339,40.563) 72.898,40.563 72.898,42.902 cw(c73.707,42.902) 73.707,43.711 76.385,43.711 ; 68.326,40.132 R15.2@68.326,41.12 ; R20.2@71.374,7.112 72.423,7.112 ccw(c72.423,7.554) 72.86,7.486 ; 72.851,12.132 72.851,12.176 cw(c73.375,12.176) 72.86,12.27 cw(c73.375,12.176) 73.375,12.7 77.212,12.7 ; 72.86,7.554 72.86,12.132 ; J2.2@74.422,25.4 76.385,25.4 ; R16.2@75.095,31.753 76.385,31.753 ; 76.385,46.548 76.385,43.711 ; 76.386,46.548 76.386,46.772 cw(c77.362,46.772) 76.672,47.462 78.155,48.945 ccw(c76.733,50.368) 78.745,50.368 78.745,54.034 ; 77.211,2.03 cw(c76.502,2.03) 76.502,1.321 61.549,1.321 ; 77.216,2.03 77.216,4.823 77.212,4.819 ; 43.768,48.006 45.212,48.006 ; 45.212,48.006 46.99,48.006 ; 46.99,48.006 54.85,48.006 ; 61.549,1.321 61.742,1.514 61.742,5.048 ; 76.385,25.4 76.708,25.4 cw(c76.708,24.892) 77.216,24.892 77.216,12.7 77.212,12.7 ; 76.385,25.4 76.385,31.753 ; 76.385,31.753 76.385,43.711 ; 77.212,4.819 77.212,12.7
  Top Layer w0.508: v2(14.002,11.884) 14.002,13.238 C18.1@14.478,13.714 ; v1(25.996,39.973) 26.004,39.965 26.004,39.046 C10.2@26.008,39.042 ; R1.2@28.274,44.12 28.473,43.92 28.473,43.332 v1@29.448,42.357 ; 50.259,13.966 51.76,12.466 ccw(c52.582,13.285) 52.605,12.125 cw(c52.613,11.617) 52.613,12.125 54.289,12.125 ; C30.1@50.32,19.558 C27.2@50.32,18.034 C25.2@50.32,16.51 C26.2@50.32,14.986 50.357,14.949 50.357,13.973 ; C27.2@50.656,18.116 53.814,18.116 cw(c53.814,17.634) 54.296,17.634 U6.2@54.296,16.3 ; C20.2@54.384,13.462 54.384,12.22 54.289,12.125 ; C28.2@56.134,12.954 56.134,12.573 cw(c55.686,12.573) 55.686,12.125 54.289,12.125
  Bottom Layer w0.381: v2(14.002,11.884) 14.011,11.874 14.011,8.595 v2(14.021,8.585)
  Bottom Layer w0.508: v1(22.098,40.767) 26.035,40.767 ; v1(25.996,39.973) 26.014,39.99 26.014,40.47 26.035,40.491 26.035,40.767 ; v1@29.441,42.34 27.868,40.767 26.035,40.767
  other v1: 29.459,42.357
5V: C16.1 C19.1 R5.1 R9.2 R11.2 R14.2 U2.5 U5.3 | length 136.8
  Top Layer w0.381: C19.1@14.732,41.15 14.969,40.913 17.705,40.913 R14.2@17.78,40.838 ; C19.1@14.732,41.833 15.24,41.833 15.57,41.833 C19.1@15.598,41.806
  Top Layer w0.508: U5.3@4.572,37.338 U5.3@5.116,37.338 6.394,37.338 ccw(c6.394,39.072) 7.62,37.846 9.432,39.658 cw(c11.121,37.969) 11.121,40.358 13.536,40.358 14.224,41.046 C19.1@14.224,41.658 ; v2(9.906,43.208) 10.887,42.228 ccw(c11.593,42.931) 11.593,41.934 13.948,41.934 C19.1@14.224,41.658 ; v2(9.906,46.99) 9.906,55.67 cw(c10.878,55.67) 10.878,56.642 79.986,56.642 cw(c79.986,55.811) 80.817,55.811 80.817,48.63 v2(80.823,48.624) ; C19.1@14.732,41.15 C19.1@14.224,41.658 ; C19.1@15.24,41.656 15.24,41.833 R5.1@15.24,43.688 ; C16.1@62.992,44.704 63.006,44.718 64.502,44.718 R11.2@64.516,44.732 R9.2@66.08,44.732 ; U2.5@63.02,43.114 C16.1@63.02,44.704 ; R9.2@66.04,44.732 66.094,44.786 66.094,45.941 cw(c66.921,45.941) 66.921,46.768 74.048,46.768 ccw(c74.049,48.26) 75.224,47.341 v2(76.492,48.608)
  Bottom Layer w0.508: v2(9.906,43.208) v2(9.906,46.99) ; v2(76.492,48.608) 80.808,48.608 v2(80.823,48.624)
GND: BT1.N C1.1 C2.1 C3.1 C4.1 C5.1 C6.1 C7.1 C8.1 C9.1 C10.1 C11.1 C12.1 C13.1 C14.1 C15.2 C16.2 C17.1 C18.2 C19.2 C20.1 C21.1 C22.1 C23.1 C24.1 C25.1 C26.1 C27.1 C28.1 C29.1 C30.2 C31.1 C32.1 C69.1 D2.1 D2.C D3.C D4.C D5.C D6.C D10.1 J1.4 J2.1 J4.6 JP1.3 JP2.1 JP3.3 JP4.1 JP5.1 JP6.1 JP7.1 R2.1 R6.1 R10.1 R12.2 SW2.2 TP1.1 U1.10 U1.19 U1.26 U1.49 U1.74 U1.99 U2.2 U3.2 U4.2 U5.2 U6.1 U6.15 U6.38 U6.G.1 U6.G.2 U6.G.4 U6.G.5 U6.G.6 U6.G.7 U6.G.8 U6.G.9 U6.G.10 U6.G.11 U6.G.12 U6.G.13 U6.G.14 U6.G.15 U6.G.16 U6.G.17 U6.G.18 U6.G.19 U6.G.20 U6.G.21 U6.G.22 U7.4 U8.2 U9.4 | length 120
  Top Layer w0.254: C18.2@14.213,19.249 C18.2@14.249,19.285 ; C9.1@21.635,32.124 21.662,32.098 22.076,32.098 cw(c22.076,31.571) 22.439,31.952 cw(c22.076,31.571) 22.448,31.944 22.47,31.922 23.501,30.891 ; C6.1@23.393,22.984 C6.1@23.419,22.959 ; 23.498,30.889 ccw(c23.929,31.32) 23.549,30.843 ccw(c23.929,31.32) 23.929,30.71 U1.10@25.721,30.71 ; v1@24.556,26.328 ccw(c24.827,26.599) 24.65,26.259 ccw(c24.827,26.599) 24.827,26.216 25.715,26.216 U1.19@25.721,26.21 ; C14.1@26.413,19.35 26.413,19.376 26.413,19.39 26.756,19.733 26.786,19.733 27.125,20.073 ; 27.129,20.07 27.229,20.17 ccw(c26.813,20.585) 27.278,20.226 ccw(c26.813,20.585) 27.337,20.319 ccw(c26.813,20.585) 27.401,20.585 U1.26@27.401,21.53 ; C10.1@27.595,39.131 27.901,38.825 U1.99@27.901,36.89 ; U1.49@38.901,21.53 38.907,21.524 38.907,20.486 ccw(c39.212,20.486) 39.212,20.18 ; 39.212,20.177 42.192,20.177 42.342,20.177 C13.1@42.404,20.24 ; U1.74@41.081,34.71 42.788,34.71 ccw(c42.789,35.472) 43.329,34.934 44.268,35.873 44.268,35.924 C11.1@44.611,36.267 44.735,36.39 C11.1@44.849,36.276 ; C7.1@46.482,34.544 C7.1@46.493,34.555 ; C15.2@58.928,42.164 U2.2@60.427,42.164 ; C15.2@59.015,41.847 C15.2@59.015,42.129
  Top Layer w0.381: C18.2@14.053,19.687 14.103,19.687 C18.2@15.24,20.823 ; C69.1@80.543,41.774 80.559,41.79 81.33,41.79 v1(81.346,41.807)
  Top Layer w0.508: v1(12.921,34.993) 14.671,34.993 14.73,35.052 14.819,34.963 v1(16.517,34.963) ; C18.2@15.24,20.823 JP2.1@15.24,24.13 ; R6.1@15.268,45.466 15.275,45.473 15.275,46.346 v1(15.283,46.353) ; v1(17.174,35.865) 17.177,35.868 18.031,35.868 C2.1@18.033,35.871 ; v1(17.687,38.126) 17.694,38.119 18.497,38.119 C1.1@18.504,38.113 ; C12.1@18.012,19.805 C12.1@18.012,20.004 ; v1(18.366,18.118) 18.372,18.124 18.372,19.799 C12.1@18.378,19.805 18.393,19.82 18.393,21.49 v1(18.407,21.505) ; C4.1@19.444,27.087 19.481,27.049 19.481,26.336 v1(19.468,26.323) ; v1(19.468,32.655) 19.47,32.653 19.47,31.784 C3.1@19.474,31.78 ; v1(19.788,40.061) 19.8,40.073 19.8,40.882 D3.C@19.812,40.894 ; v1(21.032,28.184) 21.05,28.166 21.818,28.166 C5.1@21.841,28.143 ; v1(21.332,32.873) 21.349,32.856 21.349,32.304 C9.1@21.552,32.102 ; C6.1@23.418,22.959 23.418,22.191 v1(23.436,22.173) ; v1(25.619,19.339) 25.624,19.345 26.382,19.345 C14.1@26.413,19.376 ; D2.C@25.981,17.17 26.006,17.195 26.739,17.195 v1(26.756,17.213) ; v1(27.457,45.709) 28.098,45.709 R2.1@28.224,45.835 ; v1(27.565,39.859) 27.578,39.846 27.578,39.009 C10.1@27.591,38.996 ; v1(38.455,43.781) 38.468,43.794 38.468,45.209 U7.4@38.48,45.22 ; C8.1@40.402,19.119 40.417,19.134 41.157,19.134 v1(41.172,19.149) ; C13.1@42.164,20.292 42.192,20.264 42.192,20.177 42.192,19.495 v1(42.21,19.478) ; v1(43.79,41.919) 43.796,41.914 43.796,41.142 C24.1@43.802,41.136 ; C11.1@44.849,36.276 45.38,36.276 v1(45.398,36.293) ; JP3.3@44.958,15.748 45.064,15.748 45.605,16.289 cw(c46.179,15.715) 46.179,16.527 46.246,16.527 ; 46.246,16.528 C25.1@48.74,16.528 ; C7.1@46.493,34.555 46.497,34.552 47.264,34.552 v1(47.272,34.559) ; C26.1@48.74,14.986 C25.1@48.74,16.528 ; C23.1@48.74,21.082 C27.1@48.74,18.034 C25.1@48.74,16.528 ; C25.1@48.956,16.528 C25.1@48.74,16.528 ; D5.C@49.782,27.432 49.786,27.436 50.574,27.436 v1(50.578,27.441) ; D6.C@49.782,28.956 49.784,28.958 50.569,28.958 v1(50.571,28.96) ; D4.C@49.782,25.908 v1@50.57,25.907 ; v1(50.157,53.703) 50.166,53.712 51.551,53.712 U8.2@51.56,53.721 ; v1(50.94,49.569) 50.947,49.575 51.739,49.575 C32.1@51.745,49.582 ; v1(52.012,13.477) 52.02,13.47 52.783,13.47 52.797,13.455 C20.1@52.804,13.462 52.898,13.556 52.898,16.172 U6.1@52.992,16.266 ; C31.1@56.452,49.572 56.461,49.581 57.269,49.581 v1(57.278,49.59) ; R10.1@57.493,41.841 57.498,41.835 57.498,41.041 v1(57.504,41.035) ; C28.1@57.686,13.462 57.701,13.477 58.452,13.477 v1(58.467,13.491) ; C15.2@59.015,41.847 59.038,41.824 59.038,41.076 v1(59.055,41.059) ; v1(59.427,47.417) 59.432,47.421 59.432,48.228 R12.2@59.436,48.232 ; v1(60.526,44.808) 60.544,44.791 61.176,44.791 61.392,44.575 C16.2@61.392,44.55 ; v1(60.706,2.794) C29.1@60.706,3.528 ; C17.1@60.96,48.204 60.964,48.2 60.964,47.426 v1(60.968,47.422) ; U9.4@64.894,10.414 64.898,10.418 66.441,10.418 v2(66.446,10.423) ; C21.1@68.326,45.748 68.357,45.779 69.172,45.779 v1(69.19,45.796) ; U6.15@70.502,19.051 v2@71.882,19.051 ; C22.1@73.525,31.765 73.531,31.76 73.531,30.988 v1(73.536,30.982) ; v1(79.494,4.226) 79.494,3.056 79.527,3.023 v1(79.527,1.938)
  Top Layer w0.635: U6.38@52.992,33.266 52.995,33.269 v1(52.995,34.61) ; D2.1@79.74,33.095 81.576,33.095 cw(c81.576,31.538) 82.677,32.639 ; 82.687,32.649 84.338,30.998 ; v2(83.718,30.42) 83.752,30.42 84.33,30.998 84.338,30.998 ; D10.1@86.662,26.533 86.662,28.334 ; 86.669,28.334 ccw(c85.864,28.334) 86.662,28.445 ccw(c85.864,28.334) 86.434,28.903 84.338,30.998
  Bottom Layer w0.508: v2(66.446,10.423) 66.446,8.23 66.548,8.128
  Bottom Layer w0.635: BT1.N@54.914,11.938 55.444,11.938 59.555,7.827 66.548,7.827 74.469,7.827 JP7.1@74.676,7.62
  other v1: 50.571,25.907 24.46,26.356
  other v2: 71.898,19.067
NetBT1_P: BT1.P JP7.2 U9.3 | length 21.5
  Top Layer w0.381: U9.3@64.894,9.144 64.931,9.181 66.257,9.181 cw(c66.257,8.763) 66.675,8.763 ; 66.676,8.763 66.676,6.095 ccw(c67.073,6.095) 67.073,5.698 73.244,5.698 ; 73.244,5.706 ccw(c73.244,6.194) 73.732,6.194 73.732,8.361 ; 73.734,8.361 73.734,8.619 cw(c74.566,8.619) 73.977,9.207 JP7.2@74.93,10.16
  Bottom Layer w0.381: BT1.P@70.714,11.938 73.152,11.938 74.676,10.414 JP7.2@74.93,10.414
NetC1_2: C1.2 U1.8 Y1.2 | length 9.7
  Top Layer w0.254: Y1.2@19.801,36.691 Y1.2@20.126,37.017 ; C1.2@20.084,38.113 C1.2@20.126,38.07 ; Y1.2@20.141,36.436 20.435,36.436 20.553,36.318 20.553,35.562 ccw(c21.195,35.562) 20.741,35.107 ; 20.742,35.108 23.933,31.918 ; 23.932,31.916 23.961,31.887 ccw(c24.389,32.315) 23.995,31.855 ccw(c24.389,32.315) 24.389,31.71 U1.8@25.721,31.71
  Top Layer w0.508: Y1.2@20.126,37.017 C1.2@20.126,38.07
NetC2_2: C2.2 U1.9 Y1.1 | length 8.7
  Top Layer w0.254: C2.2@18.033,34.291 C2.2@18.061,34.262 ; Y1.1@19.73,34.262 Y1.1@19.801,34.191 ; Y1.1@19.876,33.943 20.796,33.943 cw(c20.798,33.065) 21.431,33.673 21.432,33.671 23.617,31.487 ; 23.618,31.488 23.729,31.377 ccw(c24.132,31.779) 24.132,31.21 U1.9@25.721,31.21
  Top Layer w0.508: C2.2@18.061,34.262 Y1.1@19.73,34.262
NetC3_2: C3.2 U1.12 Y5.2 | length 9.7
  Top Layer w0.254: Y5.2@16.508,31.041 17.017,30.533 18.963,30.533 18.972,30.523 19.111,30.523 19.336,30.298 C3.2@19.336,30.23 ; C3.2@19.304,30.198 19.474,30.028 20.022,30.028 cw(c20.022,29.634) 20.268,29.943 ; 20.3,29.91 ccw(c20.765,30.377) 20.765,29.718 20.828,29.718 ; 20.828,29.716 U1.12@25.715,29.716
NetC4_2: C4.2 U1.13 Y5.1 | length 9.8
  Top Layer w0.254: Y5.1@16.503,27.803 17.185,28.486 19.111,28.486 19.566,28.94 19.566,28.942 20.106,28.942 ccw(c20.106,29.424) 20.447,29.083 cw(c20.754,28.776) 20.754,29.21 U1.13@25.721,29.21
NetC5_2: C5.2 JP2.2 U1.14 | length 10.8
  Top Layer w0.254: JP2.2@17.526,24.13 19.812,24.13 ccw(c19.812,24.721) 20.403,24.721 20.403,26.871 cw(c20.754,26.852) 20.754,27.203 22.291,27.203 ccw(c22.291,27.903) 22.805,27.428 23.129,27.752 23.129,27.811 C5.2@23.371,28.052 ; C5.2@23.815,28.561 23.903,28.649 ; 23.901,28.651 cw(c24.043,28.509) 23.926,28.672 cw(c24.043,28.509) 24.043,28.71 U1.14@25.721,28.71
NetC6_2: C6.2 FB1.2 R3.1 U1.21 | length 6.7
  Top Layer w0.254: C6.2@23.393,24.691 23.609,24.907 23.815,24.907 24.003,25.095 cw(c24.271,24.827) 24.271,25.206 25.717,25.206 U1.21@25.721,25.21
  Top Layer w0.305: FB1.2@21.336,24.294 FB1.2@21.6,24.294 ; FB1.2@21.412,24.37 21.555,24.514 C6.2@23.368,24.514 ; FB1.2@21.422,24.447 21.793,24.818 21.793,26.114 R3.1@21.841,26.162
NetC7_2: C7.2 U1.73 | length 4
  Top Layer w0.254: U1.73@41.081,34.21 43.162,34.21 ccw(c43.163,35.147) 43.523,34.282 ccw(c43.185,35.094) 43.808,34.473 cw(c44.131,34.148) 44.131,34.606 44.942,34.606 C7.2@44.975,34.573
NetC8_2: C8.2 U1.48 | length 2.5
  Top Layer w0.254: U1.48@38.401,21.53 38.388,21.517 38.388,20.308 ccw(c38.66,20.308) 38.468,20.116 ; 38.493,20.083 cw(c38.199,19.788) 38.615,19.788 38.615,19.765 ; 38.619,19.765 38.619,19.322 C8.2@38.822,19.119
NetC15_1: C15.1 J1.1 U2.1 | length 20.5
  Top Layer w0.254: C15.1@59.015,43.427 59.27,43.172 60.519,43.172 U2.1@60.56,43.131 ; C15.1@59.016,43.541 59.016,45.046 cw(c59.585,45.046) 59.585,45.615 63.358,45.615 ccw(c63.361,46.928) 64.339,46.051 65.377,47.089 cw(c66.302,46.164) 66.378,47.47 ccw(c66.391,47.724) 66.389,47.47 72.604,47.47 ccw(c72.604,48.15) 73.283,48.15 J1.1@73.283,49.858
NetC17_2: C17.2 J1.SH1 J1.SH2 R12.1 | length 18.5
  Top Layer w0.508: R12.1@59.436,49.812 59.45,49.798 60.946,49.798 C17.2@60.96,49.784 61,49.784 61.216,50 C17.2@61.216,50.04 ; J1.SH2@63.264,52.088 J1.SH2@63.264,52.494 ; J1.SH1@76.044,52.494 cw(c76.044,51.914) J1.SH1@76.454,52.324
  Top Layer w0.762: C17.2@61.216,50.04 J1.SH2@63.264,52.088 ; J1.SH2@63.264,52.494 J1.SH1@76.044,52.494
